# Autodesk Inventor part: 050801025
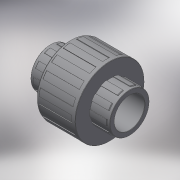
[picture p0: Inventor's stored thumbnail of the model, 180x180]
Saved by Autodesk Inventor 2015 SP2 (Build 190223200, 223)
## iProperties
Created: 2017-10
Part Number: 050801025
Material: Generic
Description: PLASSON THR.UNION+O RING PVC 2 1/2''
Document SubType Name: Modeling
Designer: KIM
Density: 1 g/cm^3
Appearance: Default
Author: KIM
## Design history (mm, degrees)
derived "050801.ipt"
feature "Solid1::050801.ipt"
tag "TaggingFeature1"
body "Solid1"
other parameters: "d3" = 72.226, "d4" = 72.226, "d5" = 90.2825, "d6" = 87.57402, "d7" = 90.2825, "d8" = 118, "d11" = 65.0034, "d14" = 22.5, "d17" = 3, "d19" = 115.64, "d20" = 3, "d21" = 1.77, "d25" = 11.8, "d26" = 5.9, "d27" = 55.8, "d28" = 0, "d32" = 11.8, "d33" = 5.9, "d35" = 0, "d39" = 0.16, "d45" = 1.35424, "d49" = 360 deg, "d51" = 1.18, "d55" = 360 deg, "d58" = 22.5, "d_" = 16, "E_" = 118, "l_" = 14, "Z_" = 11, "G_" = 72.226, "d24" = 62, "d40" = 1.35424, "d44" = 1.18
